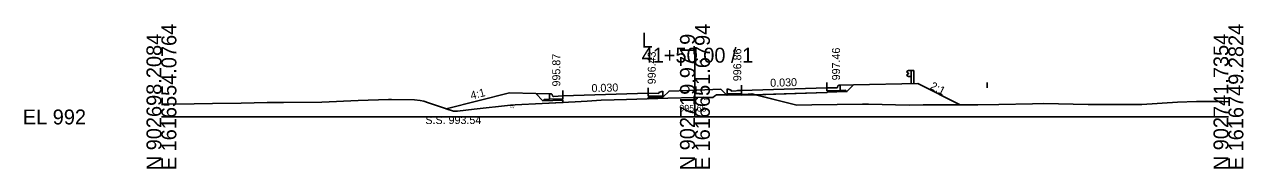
# Model space of a CAD drawing. Extents: x 1009 to 7438, y -1586 to 7964.
# Drawn here: x 4009.2 to 4237.7, y -586 to -558.9 of the extents above; entities that cross this region are included whole.
import ezdxf

# ---------------------------------------------------------------- set-up
doc = ezdxf.new("R2010")
doc.units = 0
for name, color, linetype in [('Exist Cross Section Cell', 7, 'Continuous'), ('Exist XS Center Line Elevation Label', 7, 'Continuous'), ('Exist XS Ground Line', 7, 'Continuous'), ('Prop XS Dump Level', 7, 'Continuous'), ('Prop XS Earthwork Shape', 7, 'Continuous'), ('Prop XS EOT Tick Mark', 7, 'Continuous'), ('Prop XS Finish Grade', 7, 'Continuous'), ('Prop XS Finish Grade CurbGutter', 7, 'Continuous'), ('Prop XS Finish Grade Earthwork', 7, 'Continuous'), ('Prop XS Finish Grade Pavement', 7, 'Continuous'), ('Prop XS Guardrail', 7, 'Continuous'), ('Prop XS Hydro Elevations', 7, 'Continuous'), ('Prop XS Pvmt Edge Slope', 7, 'Continuous'), ('Prop XS SE Text', 7, 'Continuous'), ('Prop XS Side Slope Text', 7, 'Continuous'), ('Prop XS SS Elevation Text', 7, 'Continuous'), ('Prop XS Subgrade CurbGutter', 7, 'Continuous'), ('Prop XS Subgrade Earthwork', 7, 'Continuous')]:
    doc.layers.add(name, color=color, linetype=linetype)

msp = doc.modelspace()

# ---------------------------------------------------------------- linework, layer by layer
at = {"layer": 'Exist Cross Section Cell'}
for p, q in [((4134.89, -576.27), (4134.89, -563.28)), ((4034.89, -576.27), (4134.89, -576.27)), ((4134.89, -576.27), (4234.89, -576.27))]:
    msp.add_line(p, q, dxfattribs=at)
at = {"layer": 'Exist XS Ground Line'}
for p, q in [((4049.85, -573.67), (4054.7, -573.58)), ((4054.7, -573.58), (4057.78, -573.53)), ((4057.78, -573.53), (4064.94, -573.47)), ((4064.94, -573.47), (4071.76, -573.21)), ((4071.76, -573.21), (4077.42, -573)), ((4077.42, -573), (4078.02, -573)), ((4078.02, -573), (4082.3, -573.03)), ((4082.3, -573.03), (4083.37, -573.21)), ((4083.37, -573.21), (4084.08, -573.33)), ((4084.08, -573.33), (4084.94, -573.61)), ((4084.94, -573.61), (4089.64, -575.18)), ((4106.28, -573.75), (4112.42, -573.45)), ((4112.42, -573.45), (4114.67, -573.29)), ((4114.67, -573.29), (4117.29, -573.12)), ((4117.29, -573.12), (4119.77, -573.05)), ((4119.77, -573.05), (4122.08, -572.97)), ((4122.08, -572.97), (4129.81, -572.76)), ((4129.81, -572.76), (4134.89, -572.62)), ((4134.89, -572.62), (4136.53, -572.58)), ((4136.53, -572.58), (4137.43, -572.59)), ((4137.43, -572.59), (4138.22, -572.59)), ((4138.22, -572.59), (4138.58, -572.37)), ((4138.58, -572.37), (4138.96, -572.11)), ((4138.96, -572.11), (4141.65, -572.08)), ((4141.65, -572.08), (4143.83, -572.04)), ((4143.83, -572.04), (4144.89, -571.98)), ((4144.89, -571.98), (4145.57, -571.94)), ((4145.57, -571.94), (4153.98, -574.05)), ((4218.64, -573.92), (4225.34, -573.52)), ((4225.34, -573.52), (4228.88, -573.34)), ((4228.88, -573.34), (4233.72, -573.36)), ((4233.72, -573.36), (4234.89, -573.42)), ((4034.89, -573.85), (4041.02, -573.81)), ((4041.02, -573.81), (4044.45, -573.77)), ((4044.45, -573.77), (4049.85, -573.67)), ((4089.64, -575.18), (4089.98, -575.18)), ((4089.98, -575.18), (4090.39, -575.18)), ((4090.39, -575.18), (4093.53, -574.83)), ((4093.53, -574.83), (4100.32, -574.07)), ((4100.32, -574.07), (4100.79, -574.04)), ((4100.79, -574.04), (4101.21, -574)), ((4101.21, -574), (4106.28, -573.75)), ((4153.98, -574.05), (4156.83, -574.01)), ((4156.83, -574.01), (4166.3, -573.84)), ((4166.3, -573.84), (4167.41, -573.85)), ((4167.41, -573.85), (4175.07, -574.05)), ((4175.07, -574.05), (4177.65, -573.99)), ((4177.65, -573.99), (4183.45, -574.02)), ((4183.45, -574.02), (4187.9, -573.99)), ((4187.9, -573.99), (4191.83, -573.9)), ((4191.83, -573.9), (4198.14, -573.82)), ((4198.14, -573.82), (4200.2, -573.77)), ((4200.2, -573.77), (4208.58, -573.9)), ((4208.58, -573.9), (4209.44, -573.91)), ((4209.44, -573.91), (4216.96, -573.93)), ((4216.96, -573.93), (4218.64, -573.92))]:
    msp.add_line(p, q, dxfattribs=at)
at = {"layer": 'Prop XS Dump Level'}
for p, q in [((4143.64, -571.28), (4159.64, -570.8)), ((4143.64, -571.28), (4159.64, -570.8)), ((4110.14, -572.28), (4126.14, -571.8)), ((4110.14, -572.28), (4126.14, -571.8))]:
    msp.add_line(p, q, dxfattribs=at)
at = {"layer": 'Prop XS Earthwork Shape'}
for points in [[(4139.74, -571.05), (4133.76, -571.32), (4130.04, -571.4), (4128.89, -572.55), (4126.14, -572.63), (4126.14, -572.72), (4126.14, -572.86), (4129.81, -572.76), (4134.89, -572.62), (4136.53, -572.58), (4137.43, -572.59), (4138.22, -572.59), (4138.58, -572.37), (4138.96, -572.11), (4140.78, -572.09)], [(4159.64, -571.63), (4163.39, -571.51), (4164.64, -570.26), (4176.64, -570.02), (4184.63, -574.01), (4183.45, -574.02), (4177.65, -573.99), (4175.07, -574.05), (4167.41, -573.85), (4166.3, -573.84), (4156.83, -574.01), (4153.98, -574.05), (4146.26, -572.11), (4159.64, -571.71)], [(4089.64, -575.18), (4089.98, -575.18), (4090.39, -575.18), (4093.53, -574.83), (4100.32, -574.07), (4100.79, -574.04), (4101.21, -574), (4106.28, -573.75), (4110.14, -573.56), (4110.14, -573.2), (4110.14, -573.11), (4106.39, -573.22), (4105.04, -571.87), (4100.14, -571.76), (4088.28, -574.73)], [(4140.99, -572.09), (4140.88, -572.19), (4140.78, -572.09)], [(4143.83, -572.04), (4144.89, -571.98), (4145.57, -571.94), (4146.26, -572.11), (4143.64, -572.19), (4143.64, -572.11), (4140.88, -572.19), (4140.99, -572.09), (4141.65, -572.08)]]:
    msp.add_lwpolyline(points, close=True, dxfattribs=at)
at = {"layer": 'Prop XS EOT Tick Mark'}
for p, q in [((4110.14, -572.28), (4110.14, -571.28)), ((4126.14, -571.8), (4126.14, -570.8)), ((4143.64, -571.28), (4143.64, -570.28)), ((4159.64, -570.8), (4159.64, -569.8))]:
    msp.add_line(p, q, dxfattribs=at)
at = {"layer": 'Prop XS Finish Grade'}
for p, q in [((4162.14, -570.32), (4164.64, -570.26)), ((4107.64, -571.92), (4105.04, -571.87))]:
    msp.add_line(p, q, dxfattribs=at)
at = {"layer": 'Prop XS Finish Grade CurbGutter'}
for p, q in [((4141.65, -571.25), (4140.9, -571)), ((4141.65, -571.42), (4141.65, -571.25)), ((4143.64, -571.28), (4141.65, -571.42)), ((4143.64, -571.28), (4142.89, -571.33)), ((4159.64, -570.8), (4161.39, -570.81)), ((4161.39, -570.81), (4161.52, -570.79)), ((4161.52, -570.79), (4161.61, -570.7)), ((4161.61, -570.7), (4161.68, -570.45)), ((4161.68, -570.45), (4161.77, -570.36)), ((4161.89, -570.32), (4161.77, -570.36)), ((4162.14, -570.32), (4161.89, -570.32)), ((4107.64, -571.92), (4107.89, -571.92)), ((4107.89, -571.92), (4108.02, -571.95)), ((4108.11, -572.04), (4108.02, -571.95)), ((4108.18, -572.29), (4108.11, -572.04)), ((4108.27, -572.38), (4108.18, -572.29)), ((4108.39, -572.4), (4108.27, -572.38)), ((4110.14, -572.28), (4108.39, -572.4)), ((4126.14, -571.8), (4128.14, -571.84)), ((4128.14, -571.67), (4128.89, -571.42)), ((4128.14, -571.84), (4128.14, -571.67))]:
    msp.add_line(p, q, dxfattribs=at)
at = {"layer": 'Prop XS Finish Grade Earthwork'}
for p, q in [((4130.04, -571.4), (4133.76, -571.32)), ((4139.74, -571.05), (4133.76, -571.32)), ((4164.64, -570.26), (4176.64, -570.02)), ((4176.64, -570.02), (4184.63, -574.01)), ((4100.14, -571.76), (4088.28, -574.73)), ((4105.04, -571.87), (4100.14, -571.76))]:
    msp.add_line(p, q, dxfattribs=at)
at = {"layer": 'Prop XS Finish Grade Pavement'}
for p, q in [((4143.64, -571.28), (4159.64, -570.8)), ((4110.14, -572.28), (4126.14, -571.8))]:
    msp.add_line(p, q, dxfattribs=at)
at = {"layer": 'Prop XS Guardrail'}
for p, q in [((4174.61, -567.74), (4174.58, -567.8)), ((4174.58, -567.8), (4174.61, -567.86)), ((4174.61, -568.35), (4174.58, -568.41)), ((4174.58, -568.41), (4174.61, -568.47)), ((4174.9, -567.54), (4174.61, -567.74)), ((4174.61, -567.86), (4174.9, -568.06)), ((4174.9, -568.15), (4174.61, -568.35)), ((4174.61, -568.47), (4174.9, -568.67)), ((4175.4, -567.54), (4174.9, -567.54)), ((4174.9, -568.06), (4174.9, -568.15)), ((4174.9, -568.67), (4175.4, -568.67)), ((4175.9, -567.54), (4175.4, -567.54)), ((4175.4, -567.54), (4175.4, -570.04)), ((4175.9, -570.04), (4175.9, -567.54))]:
    msp.add_line(p, q, dxfattribs=at)
at = {"layer": 'Prop XS Pvmt Edge Slope'}
for p, q in [((4162.14, -571.3), (4163.14, -571.27)), ((4163.14, -571.27), (4163.39, -571.51)), ((4189.64, -570.8), (4189.64, -569.8)), ((4106.64, -572.97), (4106.39, -573.22)), ((4107.64, -572.94), (4106.64, -572.97)), ((4127.64, -572.34), (4128.89, -572.3)), ((4128.64, -572.31), (4128.89, -572.55)), ((4141.14, -571.93), (4140.88, -572.19)), ((4142.14, -571.9), (4140.9, -571.94))]:
    msp.add_line(p, q, dxfattribs=at)
at = {"layer": 'Prop XS Subgrade CurbGutter'}
for p, q in [((4140.9, -571.94), (4140.9, -571)), ((4143.64, -571.28), (4143.64, -571.86)), ((4159.64, -570.8), (4159.64, -571.38)), ((4159.64, -571.38), (4162.14, -571.3)), ((4162.14, -571.3), (4162.14, -570.32)), ((4107.64, -572.94), (4107.64, -571.92)), ((4110.14, -572.86), (4107.64, -572.94)), ((4110.14, -572.28), (4110.14, -572.86)), ((4126.14, -571.8), (4126.14, -572.38)), ((4126.14, -572.38), (4127.64, -572.34)), ((4128.89, -572.3), (4128.89, -571.42)), ((4143.64, -571.86), (4142.14, -571.9))]:
    msp.add_line(p, q, dxfattribs=at)
at = {"layer": 'Prop XS Subgrade Earthwork'}
for p, q in [((4140.88, -572.19), (4139.74, -571.05)), ((4163.39, -571.51), (4164.64, -570.26)), ((4106.39, -573.22), (4105.04, -571.87)), ((4110.14, -573.11), (4106.39, -573.22)), ((4110.14, -573.2), (4110.14, -573.11)), ((4110.14, -573.2), (4110.14, -573.56)), ((4126.14, -572.63), (4128.89, -572.55)), ((4126.14, -572.72), (4126.14, -572.63)), ((4126.14, -572.72), (4126.14, -572.86)), ((4128.89, -572.55), (4130.04, -571.4)), ((4143.64, -572.11), (4140.88, -572.19)), ((4143.64, -572.19), (4159.64, -571.71)), ((4143.64, -572.19), (4143.64, -572.11)), ((4159.64, -571.63), (4163.39, -571.51)), ((4159.64, -571.71), (4159.64, -571.63))]:
    msp.add_line(p, q, dxfattribs=at)

# ---------------------------------------------------------------- texts
at = {"layer": 'Exist Cross Section Cell'}
for s, p in [('E 1616554.0764', (4037.69, -586.27)), ('E 1616651.6794', (4137.69, -586.27)), ('E 1616749.2824', (4237.69, -586.27)), ('N 902698.2084', (4034.89, -586.27)), ('N 902719.9719', (4134.89, -586.27)), ('N 902741.7354', (4234.89, -586.27))]:
    msp.add_text(s, height=2.8, rotation=90, dxfattribs=at).set_placement(p)
for s, p in [('L', (4124.89, -563.28)), ('41+50.00 / 1', (4124.89, -566.08)), ('EL 992', (4008.89, -577.67))]:
    msp.add_text(s, height=2.8, dxfattribs=at).set_placement(p)
at = {"layer": 'Exist XS Center Line Elevation Label'}
msp.add_text('995.65', height=1.25, dxfattribs=at).set_placement((4131.96, -575.25))
at = {"layer": 'Prop XS Dump Level'}
for p in [(4136.55, -573.07), (4136.55, -573.07), (4136.55, -573.07), (4100.34, -574.56)]:
    msp.add_text('Eop', height=0.3, dxfattribs=at).set_placement(p)
at = {"layer": 'Prop XS Hydro Elevations'}
for s, p in [('996.43', (4127.54, -570.13)), ('996.86', (4143.57, -569.56)), ('997.46', (4162.08, -569.4)), ('995.87', (4109.65, -570.55))]:
    msp.add_text(s, height=1.5, rotation=90, dxfattribs=at).set_placement(p)
at = {"layer": 'Prop XS SE Text'}
for p in [(4149.02, -570.62), (4115.52, -571.62)]:
    msp.add_text('0.030', height=1.5, rotation=1.7184, dxfattribs=at).set_placement(p)
at = {"layer": 'Prop XS Side Slope Text'}
for s, rotation, p in [('4:1', 14.0362, (4093, -573)), ('2:1', 333.4349, (4178.85, -570.93))]:
    msp.add_text(s, height=1.5, rotation=rotation, dxfattribs=at).set_placement(p)
at = {"layer": 'Prop XS SS Elevation Text'}
msp.add_text('S.S. 993.54', height=1.5, dxfattribs=at).set_placement((4084.36, -577.59))

doc.saveas('drawing.dxf')
